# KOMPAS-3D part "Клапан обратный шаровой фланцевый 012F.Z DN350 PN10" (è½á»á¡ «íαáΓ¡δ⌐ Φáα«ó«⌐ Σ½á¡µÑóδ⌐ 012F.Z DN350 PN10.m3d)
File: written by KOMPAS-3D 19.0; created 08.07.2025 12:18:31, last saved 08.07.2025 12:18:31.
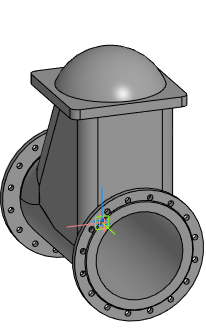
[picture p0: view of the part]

Document properties: Полное имя файла: E:\Dendor Работа Сачек\3D для проектировщиков\5.3 Тип 012F, 012F.Z Клапан обратный шаровой фланцевый\stp_Клапан обратный шаровой фланцевый 012F.Z PN10_16\Клапан обратный шаровой фланцевый 012F.Z DN350 PN10.m3d

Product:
- Part/product: Клапан обратный шаровой фланцевый 012F.Z DN350 PN10

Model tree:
1. Операция без истории:1  (labels: Клапан обратный шаровой фланцевый 012F.Z DN350 PN10)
